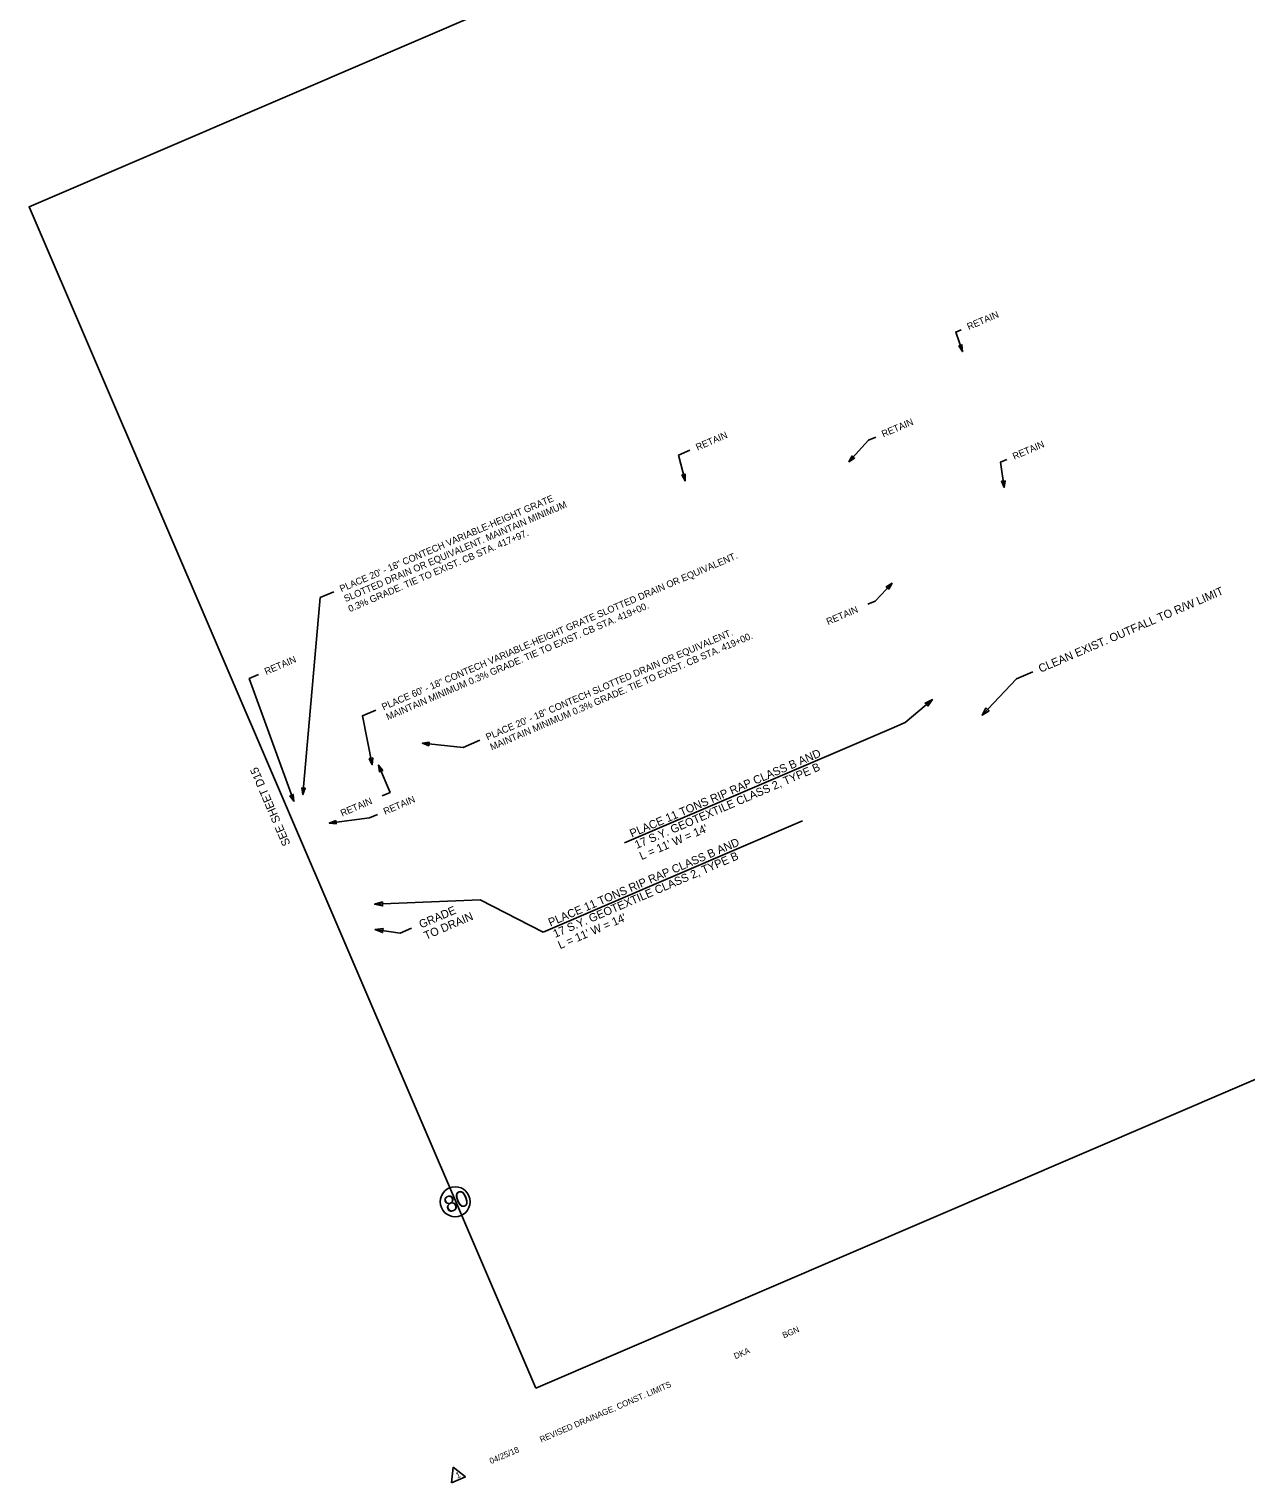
# Model space of a CAD drawing. Extents: x 1619705 to 1621490, y 1101723 to 1103701.
# Drawn here: x 1619705 to 1620598, y 1101723 to 1102790 of the extents above; entities that cross this region are included whole.
import ezdxf

# ---------------------------------------------------------------- set-up
doc = ezdxf.new("R2010")
doc.units = 0
for name, color, linetype in [('Level 2', 7, 'Continuous'), ('RD_EX_Misc', 7, 'Continuous'), ('RD_EX_RW_TX', 7, 'Continuous'), ('RD_HC_Data_Tic', 7, 'Continuous'), ('RFP', 7, 'Continuous')]:
    doc.layers.add(name, color=color, linetype=linetype)

msp = doc.modelspace()

# ---------------------------------------------------------------- linework, layer by layer
at = {"layer": 'Level 2'}
for p, q in [((1620338.2, 1102276.7), (1620142.4, 1102192.7)), ((1620272.9, 1102209), (1620082.5, 1102127.3))]:
    msp.add_line(p, q, dxfattribs=at)
for points in [[(1620389.4, 1102569.4), (1620385.4, 1102567.7), (1620390.4, 1102553.4)], [(1620326.7, 1102490.6), (1620321.3, 1102488.3), (1620307, 1102472.5)], [(1620190.3, 1102480.9), (1620182, 1102477.4), (1620186.7, 1102458.4)], [(1620422.8, 1102474.2), (1620418.3, 1102472.3), (1620421, 1102453.7)], [(1620321, 1102367.9), (1620326.3, 1102370.2), (1620338.7, 1102383.3)], [(1619928.9, 1102377), (1619919, 1102372.8), (1619906.2, 1102228.2)], [(1619873.7, 1102316.3), (1619866.9, 1102313.4), (1619899.6, 1102223.3)], [(1620441.9, 1102318.4), (1620430, 1102313.2), (1620404.8, 1102286.6)], [(1620338.2, 1102276.7), (1620348.3, 1102281.1), (1620368.3, 1102297.9)], [(1619959.8, 1102290.3), (1619949.9, 1102286.1), (1619957.1, 1102250.1)], [(1620036.2, 1102268.2), (1620023.9, 1102262.9), (1619993.9, 1102265.9)], [(1619964.4, 1102227.3), (1619970.2, 1102229.8), (1619961.7, 1102249.9)], [(1619961, 1102213.7), (1619955, 1102211.1), (1619925.6, 1102207.3)], [(1620082.5, 1102127.3), (1620036.3, 1102150.9), (1619958.8, 1102147.8)], [(1619985.9, 1102130.1), (1619977.7, 1102126.6), (1619959.2, 1102129.2)]]:
    msp.add_lwpolyline(points, dxfattribs=at)
for points in [[(1620387.6, 1102557.5), (1620390.4, 1102553.4), (1620390, 1102558.4)], [(1620309.3, 1102476.9), (1620307, 1102472.5), (1620311.2, 1102475.2)], [(1620184.3, 1102462.8), (1620186.7, 1102458.4), (1620186.8, 1102463.4)], [(1620419, 1102458.3), (1620421, 1102453.7), (1620421.6, 1102458.6)], [(1620336.3, 1102378.9), (1620338.7, 1102383.3), (1620334.4, 1102380.7)], [(1620364.9, 1102293), (1620368.3, 1102297.9), (1620362.9, 1102295.3)], [(1620407.6, 1102291.9), (1620404.8, 1102286.6), (1620409.9, 1102289.8)], [(1619998.8, 1102266.7), (1619993.9, 1102265.9), (1619998.6, 1102264.1)], [(1619954.9, 1102254.6), (1619957.1, 1102250.1), (1619957.5, 1102255.1)], [(1619964.8, 1102246), (1619961.7, 1102249.9), (1619962.4, 1102245)], [(1619905.4, 1102233.2), (1619906.2, 1102228.2), (1619907.9, 1102232.9)], [(1619896.7, 1102227.4), (1619899.6, 1102223.3), (1619899.2, 1102228.3)], [(1619930.3, 1102209.2), (1619925.6, 1102207.3), (1619930.6, 1102206.7)], [(1619964.6, 1102149.6), (1619958.8, 1102147.8), (1619964.7, 1102146.5)], [(1619965.1, 1102129.9), (1619959.2, 1102129.2), (1619964.7, 1102126.9)]]:
    msp.add_lwpolyline(points, close=True, dxfattribs=at)
at = {"layer": 'RD_EX_Misc'}
msp.add_circle((1620018, 1101929.4), 11, dxfattribs=at)
at = {"layer": 'RD_EX_RW_TX'}
for p, q in [((1620016.5, 1101734.6), (1620015.3, 1101723)), ((1620025.7, 1101727.5), (1620016.5, 1101734.6)), ((1620015.3, 1101723), (1620025.7, 1101727.5))]:
    msp.add_line(p, q, dxfattribs=at)
at = {"layer": 'RFP'}
msp.add_lwpolyline([(1620077.3, 1101792.6), (1621455.7, 1102384.2), (1621344.3, 1102622.5), (1621323.6, 1102755.5), (1621298.9, 1102749.7), (1621097, 1103220), (1620951.5, 1103157.1), (1620938.4, 1103188.8), (1619705.3, 1102659.5)], close=True, dxfattribs=at)
msp.add_lwpolyline([(1620077.3, 1101792.6), (1621455.7, 1102384.2), (1621344.3, 1102622.5), (1621323.6, 1102755.5), (1621298.9, 1102749.7), (1621097, 1103220), (1620951.5, 1103157.1), (1620938.4, 1103188.8), (1619705.3, 1102659.5)], close=True, dxfattribs=at)
msp.add_lwpolyline([(1620077.3, 1101792.6), (1621455.7, 1102384.2), (1621344.3, 1102622.5), (1621323.6, 1102755.5), (1621298.9, 1102749.7), (1621097, 1103220), (1620951.5, 1103157.1), (1620938.4, 1103188.8), (1619705.3, 1102659.5)], close=True, dxfattribs=at)
msp.add_lwpolyline([(1620077.3, 1101792.6), (1621455.7, 1102384.2), (1621344.3, 1102622.5), (1621323.6, 1102755.5), (1621298.9, 1102749.7), (1621097, 1103220), (1620951.5, 1103157.1), (1620938.4, 1103188.8), (1619705.3, 1102659.5)], close=True, dxfattribs=at)
msp.add_lwpolyline([(1620077.3, 1101792.6), (1621455.7, 1102384.2), (1621344.3, 1102622.5), (1621323.6, 1102755.5), (1621298.9, 1102749.7), (1621097, 1103220), (1620951.5, 1103157.1), (1620938.4, 1103188.8), (1619705.3, 1102659.5)], close=True, dxfattribs=at)

# ---------------------------------------------------------------- texts
at = {"layer": 'Level 2'}
for s, height, p in [('RETAIN', 5, (1620395, 1102569.1)), ('RETAIN', 5, (1620332.3, 1102490.3)), ('RETAIN', 5, (1620195.9, 1102480.6)), ('RETAIN', 5, (1620428.4, 1102473.9)), ('PLACE 20\' - 18" CONTECH VARIABLE-HEIGHT GRATE ', 5, (1619934.5, 1102376.7)), ('SLOTTED DRAIN OR EQUIVALENT. MAINTAIN MINIMUM ', 5, (1619937.6, 1102369.4)), ('0.3% GRADE. TIE TO EXIST. CB STA. 417+97.', 5, (1619940.8, 1102362)), ('PLACE 60\' - 18" CONTECH VARIABLE-HEIGHT GRATE SLOTTED DRAIN OR EQUIVALENT. ', 5, (1619965.4, 1102290)), ('CLEAN EXIST. OUTFALL TO R/W LIMIT', 6, (1620447.7, 1102317.6)), ('MAINTAIN MINIMUM 0.3% GRADE. TIE TO EXIST. CB STA. 419+00.', 5, (1619968.6, 1102282.7)), ('RETAIN', 5, (1620291.7, 1102352.6)), ('PLACE 20\' - 18" CONTECH SLOTTED DRAIN OR EQUIVALENT. ', 5, (1620041.8, 1102267.9)), ('MAINTAIN MINIMUM 0.3% GRADE. TIE TO EXIST. CB STA. 419+00.', 5, (1620044.9, 1102260.6)), ('RETAIN', 5, (1619879.3, 1102316)), ('PLACE 11 TONS RIP RAP CLASS B AND', 6, (1620147.7, 1102196.6)), ('17 S.Y. GEOTEXTILE CLASS 2, TYPE B', 6, (1620151.3, 1102188.3)), ('RETAIN', 5, (1619935.1, 1102212)), ('RETAIN', 5, (1619966.6, 1102213.3)), ("L = 11' W = 14'", 6, (1620154.8, 1102180.1)), ('PLACE 11 TONS RIP RAP CLASS B AND', 6, (1620087.9, 1102131.3)), ('17 S.Y. GEOTEXTILE CLASS 2, TYPE B', 6, (1620091.4, 1102123)), ('GRADE', 6, (1619993, 1102129.9)), ('TO DRAIN', 6, (1619996.6, 1102121.6)), ("L = 11' W = 14'", 6, (1620095, 1102114.7))]:
    msp.add_text(s, height=height, rotation=23.2284, dxfattribs=at).set_placement(p)
at = {"layer": 'RD_EX_Misc'}
msp.add_text('80', height=12, rotation=22.1585, dxfattribs=at).set_placement((1620012.7, 1101920.8))
at = {"layer": 'RD_EX_RW_TX'}
for s, p in [('BGN', (1620259.3, 1101829.1)), ('DKA', (1620223.7, 1101813.8)), ('REVISED DRAINAGE, CONST. LIMITS', (1620081.2, 1101752.6)), ('04/25/18', (1620044.3, 1101736.8)), ('1', (1620019.5, 1101726.2))]:
    msp.add_text(s, height=4.4, rotation=23.23, dxfattribs=at).set_placement(p)
at = {"layer": 'RD_HC_Data_Tic'}
msp.add_text('SEE SHEET D15', height=6, rotation=113.2284, dxfattribs=at).set_placement((1619897.2, 1102192))

doc.saveas('drawing.dxf')
